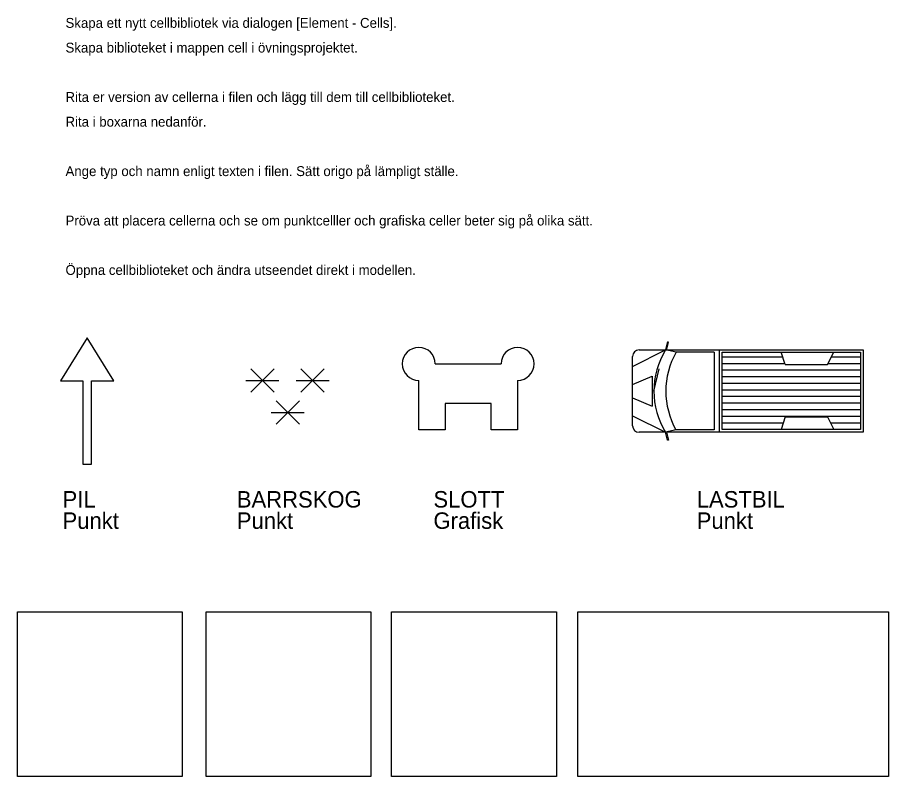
# Model space of a CAD drawing. Extents: x 1517699.5 to 1517726, y 6495354.2 to 6495377.3.
import ezdxf

# ---------------------------------------------------------------- set-up
doc = ezdxf.new("R2010")
doc.units = 0
doc.layers.add('Instruktioner', color=7, linetype='Continuous')

msp = doc.modelspace()

# ---------------------------------------------------------------- linework, layer by layer
at = {"layer": 'Instruktioner'}
for p, q in [((1517718.215, 6495366.673), (1517719.215, 6495367.173)), ((1517718.415, 6495367.173), (1517725.215, 6495367.173)), ((1517719.279, 6495367.414), (1517719.215, 6495367.173)), ((1517719.536, 6495367.104), (1517719.215, 6495367.173)), ((1517719.246, 6495367.173), (1517719.308, 6495367.407)), ((1517719.308, 6495367.407), (1517719.279, 6495367.414)), ((1517720.849, 6495364.673), (1517720.849, 6495367.173)), ((1517725.215, 6495367.173), (1517725.215, 6495364.673)), ((1517718.215, 6495364.873), (1517718.215, 6495366.973)), ((1517720.694, 6495367.11), (1517719.539, 6495367.11)), ((1517720.694, 6495367.11), (1517720.694, 6495364.746)), ((1517720.939, 6495364.763), (1517720.939, 6495367.11)), ((1517720.939, 6495367.11), (1517725.131, 6495367.11)), ((1517720.939, 6495366.966), (1517722.774, 6495366.966)), ((1517722.849, 6495366.729), (1517722.728, 6495367.11)), ((1517724.249, 6495366.966), (1517725.131, 6495366.966)), ((1517725.131, 6495367.11), (1517725.131, 6495364.763)), ((1517712.224, 6495366.751), (1517714.224, 6495366.751)), ((1517720.939, 6495366.766), (1517722.837, 6495366.766)), ((1517724.148, 6495366.766), (1517725.131, 6495366.766)), ((1517706.622, 6495365.889), (1517707.329, 6495366.597)), ((1517707.329, 6495365.889), (1517706.622, 6495366.597)), ((1517708.145, 6495365.889), (1517708.852, 6495366.597)), ((1517708.852, 6495365.889), (1517708.145, 6495366.597)), ((1517718.215, 6495366.123), (1517718.809, 6495366.374)), ((1517718.809, 6495366.374), (1517718.809, 6495365.472)), ((1517718.862, 6495365.923), (1517719.026, 6495366.605)), ((1517720.939, 6495366.566), (1517725.131, 6495366.566)), ((1517720.939, 6495366.366), (1517725.131, 6495366.366)), ((1517706.475, 6495366.243), (1517707.475, 6495366.243)), ((1517707.999, 6495366.243), (1517708.999, 6495366.243)), ((1517720.939, 6495366.166), (1517725.131, 6495366.166)), ((1517720.939, 6495365.966), (1517725.131, 6495365.966)), ((1517707.391, 6495364.923), (1517708.098, 6495365.63)), ((1517708.098, 6495364.923), (1517707.391, 6495365.63)), ((1517718.215, 6495365.723), (1517718.809, 6495365.472)), ((1517720.939, 6495365.766), (1517725.131, 6495365.766)), ((1517720.939, 6495365.566), (1517725.131, 6495365.566)), ((1517720.939, 6495365.366), (1517725.131, 6495365.366)), ((1517707.244, 6495365.277), (1517708.244, 6495365.277)), ((1517718.215, 6495365.173), (1517719.215, 6495364.673)), ((1517720.939, 6495365.166), (1517725.131, 6495365.166)), ((1517722.849, 6495365.144), (1517722.728, 6495364.763)), ((1517720.939, 6495364.966), (1517722.793, 6495364.966)), ((1517724.219, 6495364.966), (1517725.131, 6495364.966)), ((1517725.215, 6495364.673), (1517718.415, 6495364.673)), ((1517719.533, 6495364.746), (1517719.215, 6495364.673)), ((1517719.279, 6495364.431), (1517719.215, 6495364.673)), ((1517719.246, 6495364.673), (1517719.308, 6495364.439)), ((1517720.694, 6495364.746), (1517719.533, 6495364.746)), ((1517720.939, 6495364.766), (1517722.729, 6495364.766)), ((1517725.131, 6495364.763), (1517720.939, 6495364.763)), ((1517724.32, 6495364.766), (1517725.131, 6495364.766)), ((1517719.308, 6495364.439), (1517719.279, 6495364.431))]:
    msp.add_line(p, q, dxfattribs=at)
for points in [[(1517701.653, 6495367.537), (1517700.842, 6495366.234), (1517701.523, 6495366.234), (1517701.523, 6495363.709), (1517701.653, 6495363.709), (1517701.783, 6495363.709), (1517701.783, 6495366.234), (1517702.464, 6495366.234)], [(1517699.539, 6495359.224), (1517704.539, 6495359.224), (1517704.539, 6495354.224), (1517699.539, 6495354.224)], [(1517705.265, 6495359.224), (1517710.265, 6495359.224), (1517710.265, 6495354.224), (1517705.265, 6495354.224)], [(1517710.9, 6495359.224), (1517715.9, 6495359.224), (1517715.9, 6495354.224), (1517710.9, 6495354.224)], [(1517716.556, 6495359.224), (1517725.986, 6495359.224), (1517725.986, 6495354.224), (1517716.556, 6495354.224)]]:
    msp.add_lwpolyline(points, close=True, dxfattribs=at)
for points in [[(1517722.849, 6495366.729), (1517724.129, 6495366.729), (1517724.322, 6495367.11)], [(1517712.524, 6495364.751), (1517711.724, 6495364.751), (1517711.724, 6495366.251)], [(1517714.724, 6495366.251), (1517714.724, 6495364.751), (1517713.924, 6495364.751), (1517713.924, 6495365.551), (1517712.524, 6495365.551), (1517712.524, 6495364.751)], [(1517722.849, 6495365.144), (1517724.129, 6495365.144), (1517724.322, 6495364.763)]]:
    msp.add_lwpolyline(points, dxfattribs=at)
for centre, radius, start, end in [((1517711.724, 6495366.751), 0.5, 0, 270), ((1517714.724, 6495366.751), 0.5, 270, 180), ((1517718.415, 6495366.973), 0.2, 90, 180), ((1517721.256, 6495365.923), 2.394, 148.5197, 211.4804), ((1517721.617, 6495365.923), 2.394, 150.4279, 209.45), ((1517718.415, 6495364.873), 0.2, 180, 270)]:
    msp.add_arc(centre, radius, start, end, dxfattribs=at)

# ---------------------------------------------------------------- texts
for s, height, p in [('Skapa ett nytt cellbibliotek via dialogen [Element - Cells].', 0.3, (1517700.999, 6495376.951)), ('Skapa biblioteket i mappen cell i övningsprojektet.', 0.3, (1517700.999, 6495376.201)), ('Rita er version av cellerna i filen och lägg till dem till cellbiblioteket.', 0.3, (1517700.999, 6495374.701)), ('Rita i boxarna nedanför.', 0.3, (1517700.999, 6495373.951)), ('Ange typ och namn enligt texten i filen. Sätt origo på lämpligt ställe.', 0.3, (1517700.999, 6495372.451)), ('Pröva att placera cellerna och se om punktcelller och grafiska celler beter sig på olika sätt.', 0.3, (1517700.999, 6495370.951)), ('Öppna cellbiblioteket och ändra utseendet direkt i modellen.', 0.3, (1517700.999, 6495369.451)), ('PIL', 0.5, (1517700.909, 6495362.39)), ('BARRSKOG', 0.5, (1517706.2, 6495362.39)), ('SLOTT', 0.5, (1517712.169, 6495362.39)), ('LASTBIL', 0.5, (1517720.162, 6495362.39)), ('Punkt', 0.5, (1517700.909, 6495361.743)), ('Punkt', 0.5, (1517706.2, 6495361.743)), ('Grafisk', 0.5, (1517712.169, 6495361.743)), ('Punkt', 0.5, (1517720.162, 6495361.743))]:
    msp.add_text(s, height=height, dxfattribs=at).set_placement(p)

doc.saveas('drawing.dxf')
